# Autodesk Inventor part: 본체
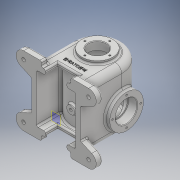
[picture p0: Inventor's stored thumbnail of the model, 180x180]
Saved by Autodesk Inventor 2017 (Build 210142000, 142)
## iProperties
Part Number: 본체
Material: 일반
Document SubType Name: Modeling
Designer: MRC
Density: 1 g/cm^3
Appearance: 기본값
Author: MRC
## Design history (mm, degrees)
sketch "스케치1"
  geometry: L1 (-45, 0)-(-45, -76); L2 (-45, -76)-(45, -76); L3 (45, -76)-(45, 0); A1 r 45 centre (0, 0) between (45, 0) and (-45, 0); 1 further point
  constraints: 6 end point, 2 point on circle, 2 tangent, 1 centre point, 1 coincident, 1 perpendicular, 1 vertical
  dimensions: "d0" = 90 diameter of A1; "d1" = 76 distance of L1.start L1.end; "d2" = 90 distance of L1.end L2.end
extrude "돌출1" new body sketch "스케치1" stored distance "d3" = 108; taper "d4" = 0 deg
node "작업 평면1"
sketch "스케치5"
  geometry: C1 r 28.5 at (0, 0); 1 further point
  constraints: 1 centre point, 1 coincident
  dimensions: "d22" = 57 diameter of C1
extrude "돌출4" join sketch "스케치5" distance "d23" = 6; taper "d24" = 0 deg
sketch "스케치6"
  geometry: C1 r 16.5 at (0, 0); 1 further point
  constraints: 1 centre point, 1 coincident
  dimensions: "d25" = 33 diameter of C1
extrude "돌출5" cut sketch "스케치6" distance "d26" = 15; taper "d27" = 0 deg
sketch "스케치7" dims "d28" = 46
  geometry: 3 further points
  constraints: 2 horizontal alignment, 1 coincident, 2 other
hole "구멍2" sketch "스케치7" at (23, 0) diameter "d29" = 3.242; stored, may be unused: countersink angle "d33" = 90 deg, drill point angle "d35" = 118 deg; dims "d30" = 8, "d31" = 4, "d32" = 2, "d34" = 10
node "작업 평면2"
node "작업 평면3"
sketch "스케치11"
  geometry: L1 (73.5, 6)-(16.5, 6) reference; C1 r 7.5 at (45, -68); 1 further point
  constraints: 1 centre point
  dimensions: "d52" = 15 diameter of C1; "d53" = 74 distance from line of L1 C1.centre
extrude "돌출7" join sketch "스케치11" stored distance "d54" = 15; taper "d55" = 0 deg
sketch "스케치12"
  geometry: C1 r 7.5 at (0, 0) reference; 2 further points
  constraints: 1 coincident
hole "구멍4" sketch "스케치12" at (0, 0) diameter "d56" = 5.188; stored, may be unused: countersink angle "d60" = 90 deg, drill point angle "d62" = 118 deg; dims "d57" = 18, "d58" = 4, "d59" = 2, "d61" = 20
node "작업 평면4"
sketch "스케치13"
  geometry: L1 (45, -76)-(-45, -76) reference; L2 (0, -76)-(20, -76); L3 (20, -76)-(20, -53); L4 (20, -53)-(-20, -53); L5 (-20, -53)-(-20, -76); 1 further point
  constraints: 8 end point, 3 perpendicular, 2 point on line, 1 midpoint
  dimensions: "d63" = 20 distance of L2.start L2.end; "d64" = 23 distance of L2.end L3.end; "d65" = 40 distance of L3.end L4.end
extrude "돌출8" cut sketch "스케치13" stored distance "d66" = 15; taper "d67" = 0 deg
node "작업 평면7"
sketch "스케치14"
  geometry: L1 (60, -64)-(-60, -64); L2 (-60, -64)-(-60, 36); L3 (-60, 36)-(60, 36); L4 (60, 36)-(60, -64); L5 (60, -64)-(-60, 36); L6 (-60, -64)-(60, 36); L7 (-60, 50)-(-27, 50); L8 (-27, 50)-(-27, 32.342); L9 (-27, 32.342)-(-36.742, 32.342); L10 (-36.742, 32.342)-(-36.742, 10.325); L11 (-36.742, 10.325)-(-65.693, 23.21); L12 (-45, -68)-(-45, 40) reference; L13 (-45, 14)-(-45, 50); A1 r 14 centre (-60, 36) between (-60, 50) and (-65.693, 23.21); 1 further point
  constraints: 24 end point, 4 perpendicular, 4 point on line, 2 horizontal, 2 midpoint, 2 parallel, 2 point on circle, 2 tangent, 1 centre point, 1 coincident
  dimensions: "d70" = 120 distance of L2.end L3.end; "d71" = 100 distance of L1.end L2.end; "d72" = 28 diameter of A1; "d73" = 18 distance between parallel lines of L8 L12; "d74" = 36 distance of L13.start L13.end
extrude "돌출9" join sketch "스케치14" distance "d75" = 12; taper "d76" = 0 deg
sketch "스케치15"
  geometry: L1 (-45, -64)-(-45, 0) reference; L2 (45, 0)-(45, -64) reference; L3 (-36, -76)-(-36, -27); L4 (36, -27)-(36, -76); L5 (-36, -76)-(36, -76); A1 r 45 centre (0, 0) between (-36, -27) and (36, -27); 2 further points
  constraints: 6 end point, 2 parallel, 2 point on circle, 1 centre point, 1 coincident, 1 horizontal, 1 point on line
  dimensions: "d77" = 9 distance between parallel lines of L3 L1; "d78" = 9 distance between parallel lines of L4 L2; "d79" = 90 diameter of A1
extrude "돌출10" cut sketch "스케치15" stored distance "d80" = 90; taper "d81" = 0 deg
sketch "스케치16"
  geometry: L1 (-6, 59.5)-(-6, 92.5) reference; L2 (0, 76)-(108, 76) reference; C1 r 31 at (68, 76); 1 further point
  constraints: 1 centre point, 1 point on line
  dimensions: "d84" = 62 diameter of C1; "d85" = 74 distance from line of L1 C1.centre
extrude "돌출11" join sketch "스케치16" stored distance "d86" = 108; taper "d87" = 0 deg
sketch "스케치17"
  geometry: C1 r 31 at (0, 0) reference; C2 r 20 at (0, 0); 1 further point
  constraints: 1 centre point, 1 coincident
  dimensions: "d88" = 40 diameter of C2
extrude "돌출12" cut sketch "스케치17" distance "d89" = 16; taper "d90" = 0 deg
node "작업 평면8"
sketch "스케치20"
  geometry: C1 r 36 at (0, 0); 1 further point
  constraints: 1 centre point, 1 coincident
extrude "돌출13" cut sketch "스케치20" stored distance "d93" = 90; taper "d94" = 0 deg
sketch "스케치22" dims "d95" = 52
  geometry: C1 r 31 at (0, 0) reference; 3 further points
  constraints: 2 vertical alignment, 1 coincident, 2 other
hole "구멍5" sketch "스케치22" at (0, 26) diameter "d96" = 3.242; stored, may be unused: countersink angle "d100" = 90 deg, drill point angle "d102" = 118 deg; dims "d97" = 8, "d98" = 4, "d99" = 2, "d101" = 10
sketch "스케치23"
  geometry: C1 r 31 at (0, 0) reference; C2 r 17.5 at (0, 0); 1 further point
  constraints: 1 centre point, 1 coincident
  dimensions: "d106" = 35 diameter of C2
extrude "돌출14" cut sketch "스케치23" stored distance "d107" = 90; taper "d108" = 0 deg
sketch "스케치24"
  geometry: C1 r 9 at (-60, 36); C2 r 9 at (60, 36); C3 r 9 at (60, -64); C4 r 9 at (-60, -64); A1 r 14 centre (-60, 36) between (-60, 50) and (-65.693, 23.21) reference; A2 r 14 centre (60, 36) between (65.693, 23.21) and (60, 50) reference; A3 r 14 centre (60, -64) between (60, -78) and (65.693, -51.21) reference; A4 r 14 centre (-60, -64) between (-65.693, -51.21) and (-60, -78) reference; 1 further point
  constraints: 4 centre point, 4 coincident
  dimensions: "d109" = 18 diameter of C1; "d110" = 18 diameter of C2; "d111" = 18 diameter of C3; "d112" = 18 diameter of C4
extrude "돌출15" cut sketch "스케치24" distance "d113" = 2; taper "d114" = 0 deg
sketch "스케치25"
  geometry: C1 r 9 at (0, 0) reference; C2 r 3.3 at (0, 0); C3 r 9 at (120, 0) reference; C4 r 3.3 at (120, 0); C5 r 9 at (120, -100) reference; C6 r 3.3 at (120, -100); C7 r 9 at (0, -100) reference; C8 r 3.3 at (0, -100); 1 further point
  constraints: 4 centre point, 4 coincident
  dimensions: "d115" = 6.6 diameter of C2; "d116" = 6.6 diameter of C4; "d117" = 6.6 diameter of C6; "d118" = 6.6 diameter of C8
extrude "돌출16" cut sketch "스케치25" stored distance "d119" = 2; taper "d120" = 0 deg
fillet "모깎기1" dims "d121" = 3
fillet "모깎기2" dims "d122" = 12
fillet "모깎기3" dims "d123" = 3
fillet "모깎기4" dims "d125" = 3
fillet "모깎기5" dims "d126" = 3
fillet "모깎기6" dims "d127" = 3
fillet "모깎기7" dims "d128" = 3
fillet "모깎기8" dims "d129" = 3
chamfer "모따기1" distance "d130" = 1; stored, may be unused: second distance "d131" = 2, angle "d132" = 45 deg
chamfer "모따기2" distance "d133" = 1; stored, may be unused: second distance "d134" = 2, angle "d135" = 45 deg
chamfer "모따기3" distance "d136" = 1; stored, may be unused: second distance "d137" = 2, angle "d138" = 45 deg
sketch "스케치26"
  geometry: L1 (-36, -27)-(-36, -31) reference; L2 (36, -31)-(36, -27) reference; L3 (-36, -27)-(-36, -76) reference; L4 (-36, -27)-(-36, -35); L5 (-36, -35)-(-28.284, -35); A1 r 45 centre (0, 0) between (-33, -30.594) and (33, -30.594) reference; A2 r 45 centre (0, 0) between (-28.634, -34.714) and (-28.284, -35); A3 r 45 centre (0, 0) between (-36, -27) and (-28.284, -35); 1 further point
  constraints: 5 point on circle, 4 end point, 2 centre point, 1 coincident, 1 horizontal, 1 point on line
  dimensions: "d140" = 8 distance from line of L1.start L5
extrude "돌출17" cut sketch "스케치26" stored distance "d141" = 70; taper "d142" = 0 deg
fillet "모깎기9" dims "d143" = 3
fillet "모깎기10" dims "d144" = 3
sketch "스케치27"
  geometry: L1 (-30, -76)-(-60, -76) reference; 2 further points
  constraints: 1 vertical alignment, 1 other
  dimensions: "d145" = 35 distance from line of L1 point (0, -41)
feature "엠보싱1" sketch "스케치27" dims "d25" = 33, "d146" = 0.5, "d147" = 0
node "솔리드1"
pattern_circular "원형 패턴2" dims angle "d37" = 360 deg
mirror "미러3"
mirror "미러4"
mirror "미러6"
pattern_circular "원형 패턴3" dims angle "d104" = 360 deg
mirror "미러7"
mirror "미러8"
mirror "미러9"
mirror "미러10"
other parameters: "d39" = -129, "d51" = -125, "d69" = -125
